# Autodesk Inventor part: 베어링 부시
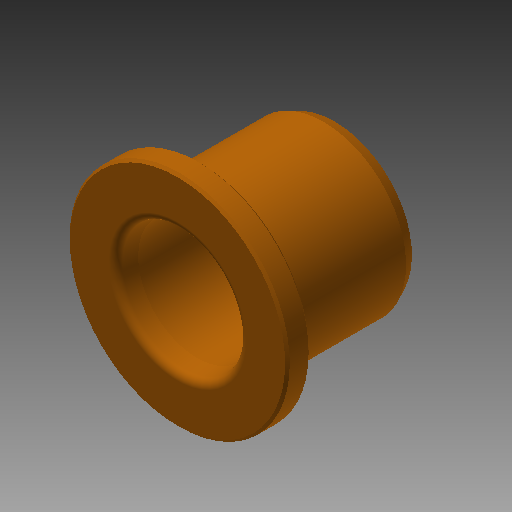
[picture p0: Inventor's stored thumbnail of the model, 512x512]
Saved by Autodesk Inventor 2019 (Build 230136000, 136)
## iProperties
Created: 2022-03
Part Number: 베어링 부시
Material: 황동, 연질
Document SubType Name: Modeling
Designer: mdu-01
Density: 1 g/cm^3
Appearance: 주황색
Author: mdu-01
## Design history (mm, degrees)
sketch "스케치1"
  geometry: L1 (0, 0)-(0, -20); L2 (7.941, 0)-(14, 0); L3 (14, 0)-(14, -3); L4 (14, -3)-(10.5, -3); L5 (10.5, -3)-(10.5, -18.6); L6 (9.844, -20)-(7.606, -20); L7 (7.5, -2.5)-(7.5, -19.4); L8 (7.5, -2.5)-(7.941, 0); L9 (7.5, -19.4)-(7.606, -20); L10 (10.5, -18.6)-(9.844, -20)
  constraints: 20 end point, 3 perpendicular, 2 horizontal alignment, 2 parallel, 1 horizontal, 1 vertical
  dimensions: "d0" = 21 diameter of L5 L1; "d2" = 28 diameter of L3 L1; "d3" = 20 distance of L1.start L1.end; "d4" = 3 distance of L2.end L3.end; "d5" = 15 diameter of L7 L1; "d6" = 10 deg angle of L7 L9; "d7" = 0.6 distance from line of L7.end L6; "d8" = 1.4 vertical distance of L5.end L6.start; "d9" = 25.0978 deg angle of L5 L10; "d10" = 10 deg angle of L7 L8; "d11" = 2.5 vertical distance of L7.start L2.start
revolve "회전1" sketch "스케치1" stored, may be unused: angle "d12" = 90 deg
chamfer "모따기1" distance "d13" = 0.3; stored, may be unused: second distance "d14" = 2, angle "d15" = 45 deg
fillet "모깎기1" dims "d16" = 0.3, "d17" = 1
node "솔리드1"
